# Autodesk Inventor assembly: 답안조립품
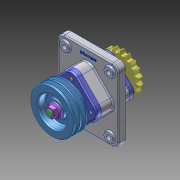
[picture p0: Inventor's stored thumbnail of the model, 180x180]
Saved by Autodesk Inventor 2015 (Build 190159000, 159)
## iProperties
Created: 2026-07
Part Number: 답안조립품
Document SubType Name: Assembly
Designer: USER
Author: USER
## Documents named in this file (12)
- C:\Users\USER\Desktop\760705V1002\답안조립품.iam
- C:\Users\USER\Desktop\760705V1002\본체.ipt
- C:\Users\USER\Desktop\760705V1002\가져온 구성요소\6각 구멍붙이 볼트 M6x16\6각 구멍붙이 볼트 M6x16.ipt
- C:\Users\USER\Desktop\760705V1002\가져온 구성요소\6각 플랜지 너트 M16\6각 플랜지 너트 M16.ipt
- C:\Users\USER\Desktop\760705V1002\가져온 구성요소\V-벨트풀리\V-벨트풀리.ipt
- C:\Users\USER\Desktop\760705V1002\가져온 구성요소\깊은 홈 볼 베어링 6206\깊은 홈 볼 베어링 6206.ipt
- C:\Users\USER\Desktop\760705V1002\가져온 구성요소\오일 실 30 45 8\오일 실 30 45 8.ipt
- C:\Users\USER\Desktop\760705V1002\가져온 구성요소\체인 스프로킷\체인 스프로킷.ipt
- C:\Users\USER\Desktop\760705V1002\가져온 구성요소\축\축.ipt
- C:\Users\USER\Desktop\760705V1002\가져온 구성요소\칼라\칼라.ipt
- C:\Users\USER\Desktop\760705V1002\가져온 구성요소\커버\커버.ipt
- C:\Users\USER\Desktop\760705V1002\가져온 구성요소\평행 키 6x6x20\평행 키 6x6x20.ipt
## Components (11 placed, 3 different names)
1. 6각 플랜지 너트 M16:1
2. V-벨트풀리:1
3. 6각 플랜지 너트 M16:2
4. 6각 구멍붙이 볼트 M6x16:1
5. 6각 구멍붙이 볼트 M6x16:3
6. 6각 구멍붙이 볼트 M6x16:4
7. 6각 구멍붙이 볼트 M6x16:5
8. 6각 구멍붙이 볼트 M6x16:2
9. 6각 구멍붙이 볼트 M6x16:6
10. 6각 구멍붙이 볼트 M6x16:7
11. 6각 구멍붙이 볼트 M6x16:8
